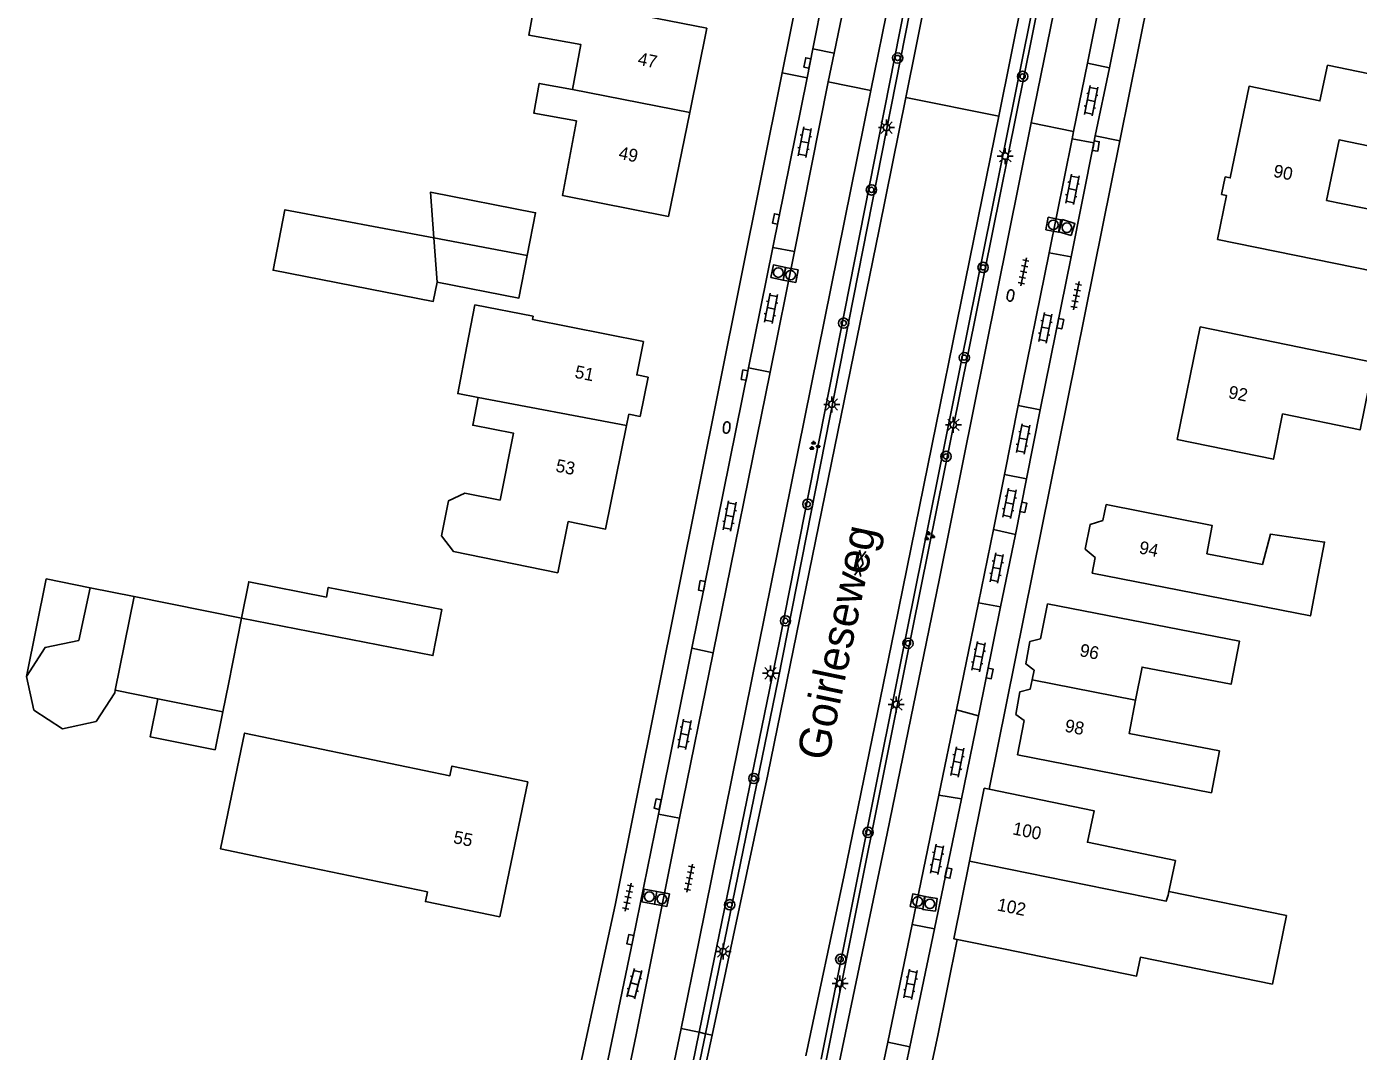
# Model space of a CAD drawing. Extents: x 131000 to 133013, y 393000 to 396501.
# Drawn here: x 132477.4 to 132581.5, y 394504 to 394584 of the extents above; entities that cross this region are included whole.
import ezdxf

# ---------------------------------------------------------------- set-up
doc = ezdxf.new("R2010")
doc.units = 0
for name, color, linetype in [('gg-anno-huisnummerreeks BGT', 7, 'Continuous'), ('gg-anno-openbare ruimte label', 7, 'Continuous'), ('gg-bbg-gedigitaliseerde bebouwing', 7, 'Continuous'), ('gg-bbg-gedigitaliseerde bijgebouw', 7, 'Continuous'), ('gg-bbg-hoofdgebouw', 7, 'Continuous'), ('gg-bbg-luifel en loopbrug', 7, 'Continuous'), ('gg-bbg-tussenscheiding', 7, 'Continuous'), ('gg-knt-verharding', 7, 'Continuous'), ('gg-knt-verharding nz', 7, 'Continuous'), ('gt-grn-groengrens', 7, 'Continuous'), ('gt-grn-weggrens', 7, 'Continuous'), ('gt-symb-boom', 7, 'Continuous'), ('gt-symb-brandkraan', 7, 'Continuous'), ('gt-symb-gesloten verharding', 7, 'Continuous'), ('gt-symb-groenvak', 7, 'Continuous'), ('gt-symb-klinker verharding', 7, 'Continuous'), ('gt-symb-kolk', 7, 'Continuous'), ('gt-symb-lichtmast', 7, 'Continuous'), ('gt-symb-rioolschacht', 7, 'Continuous'), ('gt-symb-tegel verharding', 7, 'Continuous')]:
    doc.layers.add(name, color=color, linetype=linetype)

# ---------------------------------------------------------------- blocks, each defined once
blk = doc.blocks.new('gt0-RS')
at = {"layer": 'gt-symb-rioolschacht'}
blk.add_lwpolyline([(-0.5, -0.5), (0.5, -0.5), (0.5, 0.5), (-0.5, 0.5)], close=True, dxfattribs=at)
blk.add_circle((0, 0), 0.375, dxfattribs=at)
blk = doc.blocks.new('gt0-KL1')
at = {"layer": 'gt-symb-klinker verharding'}
for p, q in [((-1.15, 0.3), (1.15, 0.3)), ((-1, -0.3), (-1, 0.3)), ((-0.5, 0.3), (-0.5, 0.45)), ((0, -0.3), (0, 0.3)), ((0.5, 0.3), (0.5, 0.45)), ((1, -0.3), (1, 0.3)), ((-1.15, -0.3), (1.15, -0.3)), ((-0.5, -0.45), (-0.5, -0.3)), ((0.5, -0.45), (0.5, -0.3))]:
    blk.add_line(p, q, dxfattribs=at)
blk = doc.blocks.new('gt0-KOLK')
at = {"layer": 'gt-symb-kolk'}
blk.add_lwpolyline([(0, 0), (0.37, 0), (0.37, 0.4), (-0.38, 0.4), (-0.38, 0), (0, 0)], dxfattribs=at)
blk = doc.blocks.new('gt0-BR')
at = {"layer": 'gt-symb-brandkraan'}
for centre, radius, start, end in [((-0.24, 0), 0.206, 107.5669, 252.4331), ((0.6, -2.66), 3, 106.892, 107.5669), ((0, -0.69), 0.938, 73.108, 106.892), ((-0.6, -2.66), 3, 72.4331, 73.108), ((0.24, 0), 0.206, 287.567, 72.4331), ((0.6, 2.66), 3, 252.4331, 253.108), ((0, 0.69), 0.938, 253.108, 286.8921), ((-0.6, 2.66), 3, 286.8921, 287.567)]:
    blk.add_arc(centre, radius, start, end, dxfattribs=at)
blk = doc.blocks.new('gt0-BOOM')
at = {"layer": 'gt-symb-boom'}
for radius in [0.4, 0.2]:
    blk.add_circle((0, 0), radius, dxfattribs=at)
blk = doc.blocks.new('gt0-TEG1')
at = {"layer": 'gt-symb-tegel verharding'}
for p, q in [((-1.12, 0), (1.12, 0)), ((-0.9, -0.25), (-0.9, 0.25)), ((-0.45, -0.25), (-0.45, 0.25)), ((0, -0.25), (0, 0.25)), ((0.45, -0.25), (0.45, 0.25)), ((0.9, -0.25), (0.9, 0.25))]:
    blk.add_line(p, q, dxfattribs=at)
blk = doc.blocks.new('gt0-LMAST')
at = {"layer": 'gt-symb-lichtmast'}
for p, q in [((-0.18, 0.17), (-0.45, 0.44)), ((-0.01, 0.25), (-0.01, 0.62)), ((0.17, 0.17), (0.44, 0.44)), ((-0.26, 0), (-0.63, 0)), ((-0.18, -0.18), (-0.45, -0.45)), ((-0.01, -0.25), (-0.01, -0.63)), ((0.44, -0.45), (0.17, -0.18)), ((0.24, 0), (0.62, 0))]:
    blk.add_line(p, q, dxfattribs=at)
blk.add_circle((-0.01, 0), 0.25, dxfattribs=at)
blk = doc.blocks.new('gt0-GESVH1')
at = {"layer": 'gt-symb-gesloten verharding'}
for p, q in [((-0.99, -0.26), (0.01, 0.24)), ((0.01, -0.26), (-0.99, 0.24)), ((0.01, 0.24), (1.01, -0.26)), ((1.01, 0.24), (0.01, -0.26))]:
    blk.add_line(p, q, dxfattribs=at)
blk = doc.blocks.new('gt0-GRVAK')
at = {"layer": 'gt-symb-groenvak'}
for p, q in [((-0.11, 0.19), (-0.23, 0.24)), ((-0.18, 0.15), (0.09, 0.15)), ((-0.09, 0.21), (-0.16, 0.32)), ((-0.05, 0.21), (-0.05, 0.39)), ((0, 0.21), (0.06, 0.32)), ((0.02, 0.19), (0.13, 0.24)), ((0.26, -0.05), (0.2, 0.06)), ((0.31, -0.05), (0.31, 0.13)), ((0.35, -0.05), (0.41, 0.06)), ((-0.24, -0.23), (-0.36, -0.18)), ((-0.32, -0.26), (-0.05, -0.26)), ((-0.23, -0.21), (-0.29, -0.09)), ((-0.18, -0.2), (-0.18, -0.02)), ((-0.14, -0.21), (-0.07, -0.09)), ((-0.12, -0.23), (0, -0.18)), ((0.24, -0.07), (0.12, -0.02)), ((0.17, -0.11), (0.44, -0.11)), ((0.37, -0.07), (0.49, -0.02))]:
    blk.add_line(p, q, dxfattribs=at)

msp = doc.modelspace()

# ---------------------------------------------------------------- linework, layer by layer
at = {"layer": 'gg-bbg-gedigitaliseerde bebouwing'}
for p, q in [((132552.21, 394524.53), (132552.6, 394524.45)), ((132496.59, 394518.94), (132508.68, 394516.43)), ((132575.83, 394514.59), (132566.64, 394516.46))]:
    msp.add_line(p, q, dxfattribs=at)
for points in [[(132530.53, 394583.93), (132521.82, 394585.63), (132521.87, 394585.94), (132517.23, 394586.79), (132516.6, 394583.39), (132520.68, 394582.64), (132520.03, 394579.13)], [(132579.03, 394581.04), (132599.87, 394576.74), (132598.75, 394571.33), (132579.95, 394575.19), (132578.97, 394570.45)], [(132520.03, 394579.13), (132517.43, 394579.61), (132517, 394577.29), (132520.33, 394576.68), (132519.25, 394570.84), (132527.53, 394569.22)], [(132570.43, 394567.42), (132585.68, 394564.32), (132586.61, 394568.89), (132578.97, 394570.45)], [(132525.58, 394559.43), (132516.89, 394561.17), (132516.94, 394561.42), (132512.4, 394562.3), (132511.77, 394559.08)], [(132575.52, 394553.78), (132581.59, 394552.53), (132582.67, 394557.81), (132569.08, 394560.59)], [(132511.77, 394559.08), (132511.05, 394555.37), (132512.65, 394555.06)], [(132512.65, 394555.06), (132512.23, 394552.89), (132515.4, 394552.28), (132514.38, 394547.05)], [(132575.52, 394553.78), (132574.81, 394550.24), (132567.28, 394551.77)], [(132514.38, 394547.05), (132511.6, 394547.59), (132510.32, 394546.98), (132509.77, 394544.25), (132510.71, 394543.03), (132518.88, 394541.37)], [(132561.74, 394546.71), (132570.03, 394545.05), (132569.61, 394542.85), (132573.96, 394542.02)], [(132578.32, 394541.19), (132578.81, 394543.76), (132574.59, 394544.39), (132573.96, 394542.02)], [(132578.32, 394541.19), (132577.71, 394537.99), (132560.64, 394541.33)], [(132557.14, 394538.95), (132572.15, 394536.03), (132571.5, 394532.65), (132564.55, 394534), (132564.04, 394531.4)], [(132564.04, 394531.4), (132563.54, 394528.8), (132570.59, 394527.44), (132569.96, 394524.18), (132554.81, 394527.13)], [(132516.52, 394525.03), (132510.6, 394526.26), (132510.44, 394525.5), (132494.39, 394528.84), (132492.51, 394519.79), (132496.59, 394518.94)], [(132552.6, 394524.45), (132560.79, 394522.77), (132560.27, 394520.31), (132567.15, 394518.87), (132566.64, 394516.46)], [(132508.68, 394516.43), (132508.52, 394515.67), (132514.33, 394514.47)]]:
    msp.add_lwpolyline(points, dxfattribs=at)
at = {"layer": 'gg-bbg-gedigitaliseerde bijgebouw'}
for p, q in [((132482.32, 394540.2), (132481.43, 394536.06)), ((132485.75, 394539.51), (132482.32, 394540.2)), ((132484.28, 394532.19), (132485.75, 394539.51)), ((132484.24, 394531.99), (132484.28, 394532.19)), ((132487.62, 394531.52), (132492.69, 394530.49))]:
    msp.add_line(p, q, dxfattribs=at)
for points in [[(132509.18, 394567.54), (132508.92, 394571.11), (132517.14, 394569.51), (132516.49, 394566.17)], [(132509.18, 394567.54), (132497.54, 394569.74), (132496.62, 394565.01), (132509.14, 394562.57), (132509.44, 394564.08)], [(132516.49, 394566.17), (132515.83, 394562.83), (132509.44, 394564.08)], [(132494.16, 394537.81), (132509.11, 394534.9), (132509.82, 394538.49), (132500.93, 394540.22), (132500.79, 394539.47), (132494.71, 394540.66), (132494.16, 394537.81)], [(132477.35, 394533.25), (132478.79, 394535.53), (132481.43, 394536.06)], [(132484.24, 394531.99), (132482.78, 394529.74), (132480.16, 394529.18), (132477.91, 394530.63), (132477.35, 394533.25)], [(132492.69, 394530.49), (132492.09, 394527.53), (132487.02, 394528.54), (132487.62, 394531.52)]]:
    msp.add_lwpolyline(points, dxfattribs=at)
at = {"layer": 'gg-bbg-hoofdgebouw'}
for p, q in [((132530.53, 394583.93), (132529.19, 394577.35)), ((132529.19, 394577.35), (132527.53, 394569.22)), ((132567.28, 394551.77), (132569.08, 394560.59)), ((132561.48, 394545.45), (132561.74, 394546.71)), ((132560.64, 394541.33), (132560.89, 394542.55)), ((132556.6, 394536.21), (132557.14, 394538.95)), ((132554.81, 394527.13), (132555.34, 394529.82)), ((132516.52, 394525.03), (132514.33, 394514.47)), ((132551.05, 394518.82), (132552.21, 394524.53)), ((132550.08, 394512.71), (132553.85, 394511.94))]:
    msp.add_line(p, q, dxfattribs=at)
for points in [[(132579.03, 394581.04), (132578.45, 394578.24), (132572.91, 394579.39), (132571.44, 394572.23), (132571.05, 394572.31), (132570.76, 394570.93), (132571.15, 394570.85), (132570.43, 394567.42)], [(132525.58, 394559.43), (132525.05, 394556.83), (132525.93, 394556.65), (132525.31, 394553.58), (132524.43, 394553.76), (132524.25, 394552.88)], [(132524.25, 394552.88), (132522.61, 394544.78), (132519.69, 394545.37), (132518.88, 394541.37)], [(132560.89, 394542.55), (132560.1, 394543.22), (132560.5, 394545.15), (132561.48, 394545.45)], [(132555.96, 394533.01), (132556.11, 394533.75), (132555.46, 394534.24), (132555.78, 394536), (132556.6, 394536.21)], [(132555.34, 394529.82), (132554.68, 394530.3), (132555, 394532.07), (132555.81, 394532.28), (132555.96, 394533.01)], [(132550.08, 394512.71), (132549.82, 394512.76), (132551.05, 394518.82)], [(132553.85, 394511.94), (132564.12, 394509.85), (132564.42, 394511.32), (132574.74, 394509.22), (132575.83, 394514.59)]]:
    msp.add_lwpolyline(points, dxfattribs=at)
at = {"layer": 'gg-bbg-luifel en loopbrug'}
for p, q in [((132494.16, 394537.81), (132485.75, 394539.51)), ((132494.16, 394537.81), (132493.13, 394532.67)), ((132487.62, 394531.52), (132484.28, 394532.19)), ((132493.13, 394532.67), (132492.69, 394530.49))]:
    msp.add_line(p, q, dxfattribs=at)
msp.add_lwpolyline([(132482.32, 394540.2), (132478.89, 394540.89), (132477.35, 394533.25)], dxfattribs=at)
at = {"layer": 'gg-bbg-tussenscheiding'}
for p, q in [((132529.19, 394577.35), (132520.03, 394579.13)), ((132509.44, 394564.08), (132509.18, 394567.54)), ((132516.49, 394566.17), (132509.18, 394567.54)), ((132524.25, 394552.88), (132512.65, 394555.06)), ((132564.04, 394531.4), (132555.96, 394533.01)), ((132566.58, 394516.17), (132566.64, 394516.46))]:
    msp.add_line(p, q, dxfattribs=at)
msp.add_lwpolyline([(132566.58, 394516.17), (132566.44, 394515.71), (132551.05, 394518.82)], dxfattribs=at)
at = {"layer": 'gg-knt-verharding'}
for p, q in [((132570.73, 394751.79), (132536.42, 394580.45)), ((132583.09, 394675.81), (132562.81, 394575.13)), ((132549.67, 394610.36), (132543.35, 394579.05)), ((132553.34, 394577.04), (132559.63, 394608.4)), ((132562.21, 394607.9), (132555.88, 394576.53)), ((132540.54, 394590.99), (132538.81, 394582.32)), ((132540.47, 394581.97), (132542.25, 394590.65)), ((132560.29, 394581.19), (132561.99, 394589.7)), ((132563.71, 394589.36), (132561.99, 394580.84)), ((132538.81, 394582.32), (132538.36, 394580.06)), ((132540.02, 394579.73), (132540.47, 394581.97)), ((132559.19, 394575.86), (132560.29, 394581.19)), ((132561.99, 394580.84), (132560.89, 394575.52)), ((132538.36, 394580.06), (132535.68, 394566.8)), ((132537.37, 394566.47), (132540.02, 394579.73)), ((132559.07, 394575.28), (132559.19, 394575.86)), ((132560.89, 394575.52), (132560.78, 394574.96)), ((132562.81, 394575.13), (132552.6, 394524.45)), ((132557.28, 394566.36), (132559.07, 394575.28)), ((132560.78, 394574.96), (132559, 394566.05)), ((132535.68, 394566.8), (132533.78, 394557.38)), ((132535.47, 394557.05), (132537.37, 394566.47)), ((132554.87, 394554.45), (132557.28, 394566.36)), ((132559, 394566.05), (132556.58, 394554.1)), ((132533.78, 394557.38), (132529.35, 394535.48)), ((132531.03, 394535.12), (132535.47, 394557.05)), ((132553.79, 394549.04), (132554.87, 394554.45)), ((132556.58, 394554.1), (132555.5, 394548.71)), ((132552.92, 394544.74), (132553.79, 394549.04)), ((132555.5, 394548.71), (132554.64, 394544.36)), ((132551.76, 394539.01), (132552.92, 394544.74)), ((132554.64, 394544.36), (132553.48, 394538.71)), ((132551.76, 394539.01), (132550.05, 394530.65)), ((132553.48, 394538.71), (132551.75, 394530.19)), ((132529.35, 394535.48), (132526.74, 394522.51)), ((132528.39, 394522.18), (132531.03, 394535.12)), ((132548.67, 394523.99), (132550.05, 394530.65)), ((132551.75, 394530.19), (132550.42, 394523.69)), ((132546.58, 394513.87), (132548.67, 394523.99)), ((132550.42, 394523.69), (132548.31, 394513.53)), ((132544.68, 394504.67), (132546.58, 394513.87)), ((132548.31, 394513.53), (132546.4, 394504.32)), ((132543.76, 394500.35), (132544.68, 394504.67)), ((132546.4, 394504.32), (132545.47, 394500))]:
    msp.add_line(p, q, dxfattribs=at)
for points in [[(132552.31, 394609.84), (132551.99, 394607.91), (132546.08, 394578.51)], [(132509.75, 394454.14), (132509.61, 394454.23), (132512.04, 394464.16), (132515.39, 394478.72), (132523.35, 394515.39), (132536.42, 394580.45)], [(132543.35, 394579.05), (132529.91, 394512.53), (132528.52, 394505.76)], [(132546.08, 394578.51), (132544, 394568.2), (132535.3, 394525.59), (132530.93, 394505.23)], [(132538.25, 394503.61), (132541.25, 394517.74), (132545.19, 394536.93), (132553.34, 394577.04)], [(132555.88, 394576.53), (132548.71, 394540.93), (132544.63, 394521), (132540.87, 394503.03)], [(132512.69, 394458.45), (132515.5, 394470.31), (132519.11, 394486.35), (132522.11, 394500), (132524.74, 394512.65), (132526.74, 394522.51)], [(132514.37, 394458.04), (132517.21, 394469.92), (132522.24, 394492.28), (132523.9, 394500), (132525.02, 394505.39), (132528.39, 394522.18)], [(132538.44, 394459.65), (132539.92, 394466.94), (132540.21, 394466.88), (132543.55, 394481.92), (132548.57, 394505.21), (132550.08, 394512.71)], [(132519.25, 394464.04), (132520.35, 394468.73), (132524.22, 394485.79), (132527.33, 394500), (132528.52, 394505.76)], [(132522.01, 394464.79), (132524.82, 394477.61), (132527.65, 394490.1), (132530.93, 394505.23)]]:
    msp.add_lwpolyline(points, dxfattribs=at)
at = {"layer": 'gg-knt-verharding nz'}
for p, q in [((132540.47, 394581.97), (132538.81, 394582.32)), ((132560.29, 394581.19), (132561.99, 394580.84)), ((132559.07, 394575.28), (132560.78, 394574.96)), ((132537.37, 394566.47), (132535.68, 394566.8)), ((132557.28, 394566.36), (132559, 394566.05)), ((132535.47, 394557.05), (132533.78, 394557.38)), ((132554.87, 394554.45), (132556.58, 394554.1)), ((132553.79, 394549.04), (132555.5, 394548.71)), ((132552.92, 394544.74), (132554.64, 394544.36)), ((132551.76, 394539.01), (132553.48, 394538.71)), ((132531.03, 394535.12), (132529.35, 394535.48)), ((132550.05, 394530.65), (132551.75, 394530.19)), ((132548.67, 394523.99), (132550.42, 394523.69)), ((132528.39, 394522.18), (132526.74, 394522.51)), ((132546.58, 394513.87), (132548.31, 394513.53)), ((132544.68, 394504.67), (132546.4, 394504.32))]:
    msp.add_line(p, q, dxfattribs=at)
at = {"layer": 'gt-grn-groengrens'}
for p, q in [((132528.52, 394505.76), (132529.93, 394505.45)), ((132529.93, 394505.45), (132530.41, 394505.34)), ((132530.41, 394505.34), (132530.93, 394505.23))]:
    msp.add_line(p, q, dxfattribs=at)
for points in [[(132551.01, 394610.09), (132546.78, 394589.64), (132536.21, 394536.01), (132529.93, 394505.45)], [(132551.4, 394610.02), (132548.6, 394596.47), (132536.09, 394533.02), (132530.41, 394505.34)], [(132560.56, 394608.22), (132546.21, 394537.04), (132539.45, 394503.34)], [(132560.95, 394608.15), (132546.6, 394536.96), (132539.84, 394503.26)], [(132529.93, 394505.45), (132528.07, 394496.39), (132525.93, 394486.25), (132523.73, 394476.66), (132521.01, 394465.23), (132520.25, 394463.81)], [(132530.41, 394505.34), (132529.56, 394501.2), (132526.74, 394486.86), (132521.77, 394464.92), (132521.07, 394463.62)]]:
    msp.add_lwpolyline(points, dxfattribs=at)
at = {"layer": 'gt-grn-weggrens'}
for p, q in [((132538.36, 394580.06), (132536.42, 394580.45)), ((132540.02, 394579.73), (132543.35, 394579.05)), ((132553.34, 394577.04), (132546.08, 394578.51)), ((132559.19, 394575.86), (132555.88, 394576.53)), ((132562.81, 394575.13), (132560.89, 394575.52))]:
    msp.add_line(p, q, dxfattribs=at)

# ---------------------------------------------------------------- block references
at = {"layer": 'gt-symb-boom'}
for p in [(132545.44, 394581.6), (132555.21, 394580.16), (132543.39, 394571.29), (132552.12, 394565.23), (132541.22, 394560.88), (132550.65, 394558.18), (132549.22, 394550.46), (132538.42, 394546.72), (132536.67, 394537.61), (132546.25, 394535.85), (132534.2, 394525.29), (132543.13, 394521.08), (132532.31, 394515.42), (132540.99, 394511.16)]:
    msp.add_blockref('gt0-BOOM', p, dxfattribs=at)
at = {"layer": 'gt-symb-brandkraan'}
for p, rotation in [((132554.26, 394563.04), 80.33049474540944), ((132532.07, 394552.72), 81.02737338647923)]:
    msp.add_blockref('gt0-BR', p, dxfattribs=dict(at, rotation=rotation))
at = {"layer": 'gt-symb-gesloten verharding', "rotation": -101.36613785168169}
msp.add_blockref('gt0-GESVH1', (132542.52, 394542.11), dxfattribs=at)
at = {"layer": 'gt-symb-groenvak'}
for p in [(132538.92, 394551.29), (132547.89, 394544.22)]:
    msp.add_blockref('gt0-GRVAK', p, dxfattribs=at)
at = {"layer": 'gt-symb-klinker verharding'}
for p, rotation in [((132560.56, 394578.26), -101.13011108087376), ((132538.18, 394575.02), -100.83791044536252), ((132559.1, 394571.33), -101.13011108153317), ((132535.54, 394562.03), -100.83791044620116), ((132556.98, 394560.51), -101.13011108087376), ((132555.25, 394551.83), -101.13011108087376), ((132554.18, 394546.79), -101.13011108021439), ((132532.3, 394545.8), -100.83791044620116), ((132553.18, 394541.73), -101.13011108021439), ((132551.76, 394534.82), -101.13011108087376), ((132528.79, 394528.74), -100.83791044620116), ((132550.1, 394526.58), -101.13011108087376), ((132548.52, 394518.96), -101.13011108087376), ((132524.86, 394509.25), -104.59195620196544), ((132546.45, 394509.21), -101.13011108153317)]:
    msp.add_blockref('gt0-KL1', p, dxfattribs=dict(at, rotation=rotation))
at = {"layer": 'gt-symb-kolk'}
for p, rotation in [((132538.58, 394581.18), 78.46537934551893), ((132560.74, 394574.74), -99.15139601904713), ((132536.12, 394568.99), 78.57767893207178), ((132557.95, 394560.86), -101.36613785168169), ((132533.67, 394556.78), 79.63367739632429), ((132555.07, 394546.52), -101.1863292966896), ((132530.33, 394540.31), 78.52151796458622), ((132552.44, 394533.53), -101.36613785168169), ((132526.88, 394523.25), 78.57767892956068), ((132549.21, 394517.93), -101.82670392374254), ((132524.74, 394512.65), 78.59511272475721)]:
    msp.add_blockref('gt0-KOLK', p, dxfattribs=dict(at, rotation=rotation))
at = {"layer": 'gt-symb-lichtmast'}
for p in [(132544.58, 394576.16), (132553.86, 394573.93), (132540.31, 394554.53), (132549.8, 394552.93), (132535.51, 394533.51), (132545.34, 394531.08), (132531.8, 394511.77), (132540.94, 394509.27)]:
    msp.add_blockref('gt0-LMAST', p, dxfattribs=at)
at = {"layer": 'gt-symb-rioolschacht'}
for p, rotation in [((132557.61, 394568.56), -10.89418298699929), ((132558.67, 394568.34), 73.19645197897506), ((132536.11, 394564.83), -12.062746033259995), ((132537.07, 394564.63), 79.51061018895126), ((132526.03, 394516.05), -100.89418298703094), ((132527.01, 394515.87), 169.16208955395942), ((132547.01, 394515.68), -11.242525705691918), ((132547.96, 394515.49), -97.70065539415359)]:
    msp.add_blockref('gt0-RS', p, dxfattribs=dict(at, rotation=rotation))
at = {"layer": 'gt-symb-tegel verharding'}
for p, rotation in [((132555.28, 394564.88), -101.42232107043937), ((132559.4, 394563.02), -101.42232107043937), ((132529.17, 394517.5), 78.6338621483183), ((132524.37, 394516.02), -102.06274602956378)]:
    msp.add_blockref('gt0-TEG1', p, dxfattribs=dict(at, rotation=rotation))

# ---------------------------------------------------------------- texts
at = {"layer": 'gg-anno-huisnummerreeks BGT'}
for s, rotation, p in [('47', 348.5, (132525.07, 394581.08)), ('49', 348.5, (132523.57, 394573.73)), ('90', 348.4, (132574.75, 394572.32)), ('51', 348.5, (132520.14, 394556.62)), ('92', 348.5, (132571.23, 394555.03)), ('53', 348.5, (132518.65, 394549.29)), ('94', 348.4, (132564.25, 394542.89)), ('96', 348.7, (132559.61, 394534.86)), ('98', 349, (132558.45, 394528.96)), ('100', 348.5, (132554.37, 394520.93)), ('55', 348.3, (132510.65, 394520.25)), ('102', 348.5, (132553.16, 394514.98))]:
    msp.add_text(s, height=1, rotation=rotation, dxfattribs=at).set_placement(p)
at = {"layer": 'gg-anno-openbare ruimte label'}
msp.add_text('Goirleseweg', height=2.5, rotation=78.2, dxfattribs=at).set_placement((132539.99, 394526.58))

doc.saveas('drawing.dxf')
